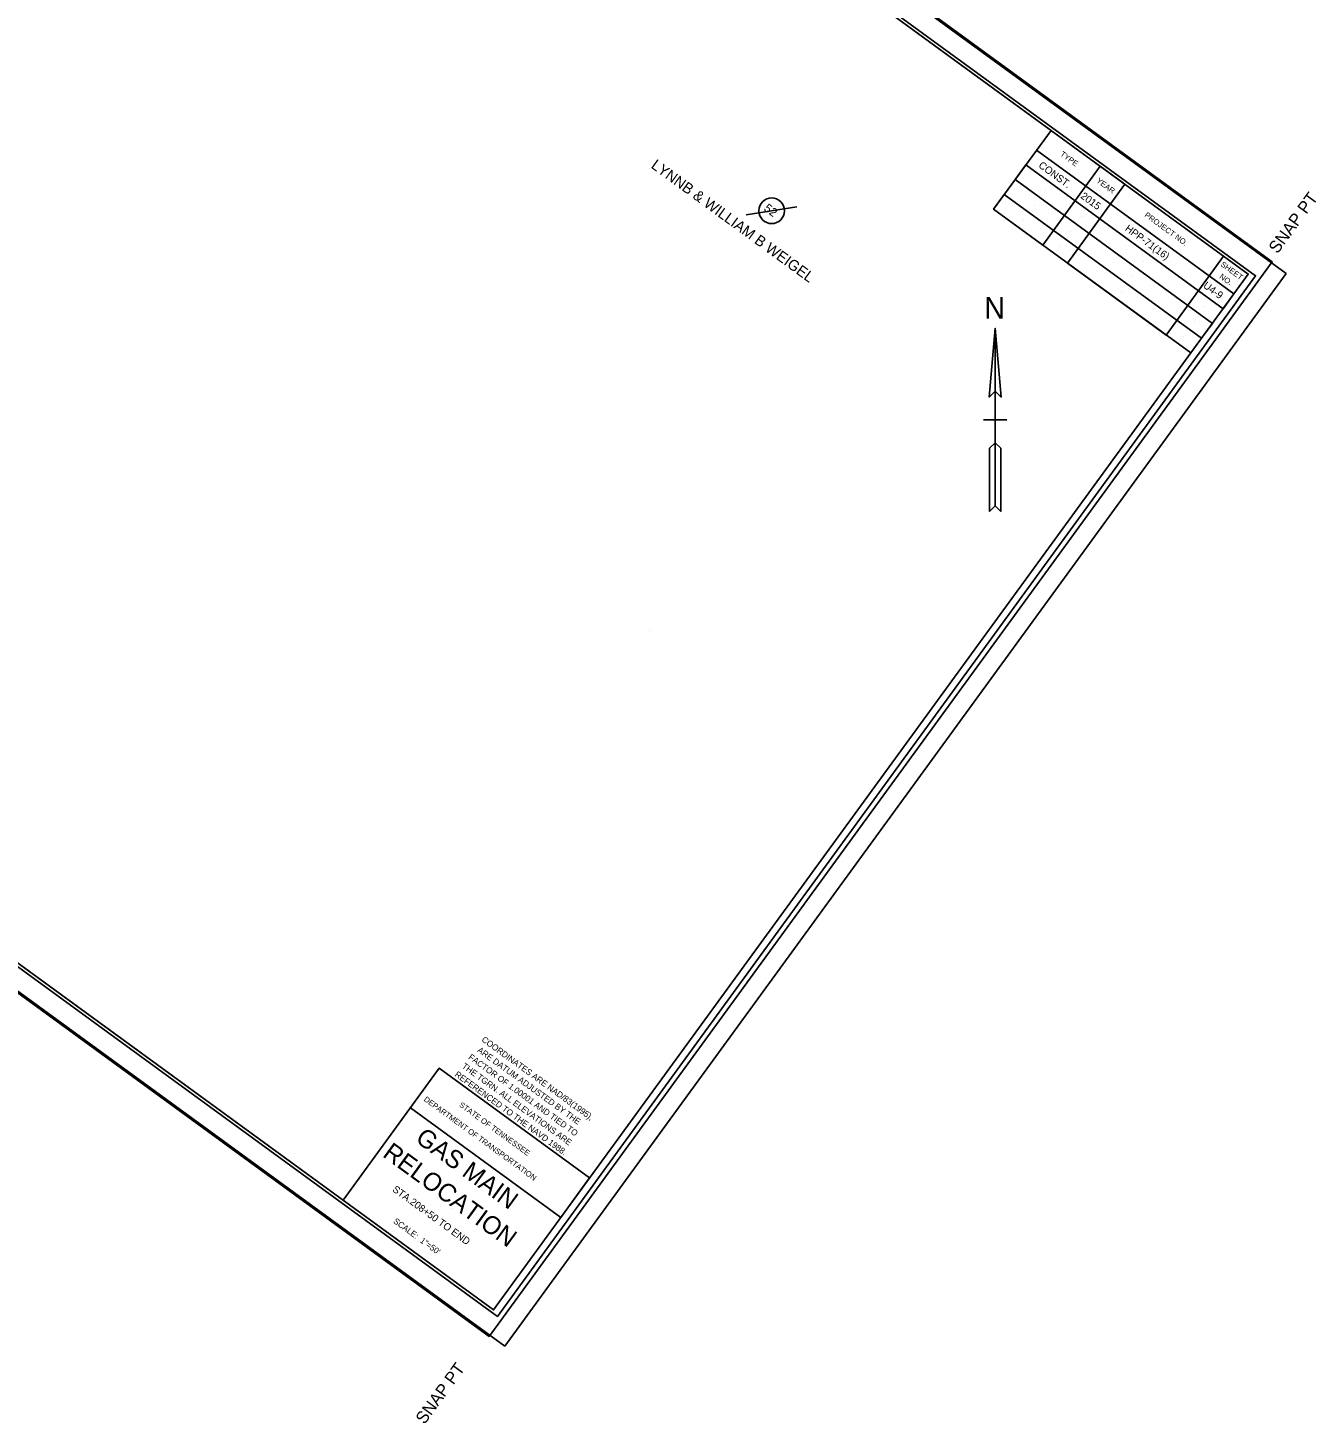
# Model space of a CAD drawing. Extents: x 2632015 to 2634135, y 566161 to 568172.
# Drawn here: x 2633079 to 2634135, y 566161 to 567305 of the extents above; entities that cross this region are included whole.
import ezdxf

# ---------------------------------------------------------------- set-up
doc = ezdxf.new("R2010")
doc.units = 0
for name, color, linetype in [('DESIGN - CENTERLINE - Proposed Text', 7, 'Continuous'), ('DESIGN - SCRATCH - User 1', 7, 'Continuous'), ('DESIGN - SHEET - Corner Text', 7, 'Continuous'), ('DESIGN - SHEET - Light Grid', 7, 'Continuous'), ('DESIGN - SHEET - Linework', 7, 'Continuous'), ('DESIGN - SHEET - Plot Shape', 7, 'Continuous'), ('SURVEY - PROPERTY - Owners', 7, 'Continuous'), ('SURVEY - PROPERTY - Tract Numbers', 7, 'Continuous')]:
    doc.layers.add(name, color=color, linetype=linetype)

msp = doc.modelspace()

# ---------------------------------------------------------------- linework, layer by layer
at = {"layer": 'DESIGN - CENTERLINE - Proposed Text'}
for p, q in [((2633871.9, 566983.6), (2633862.4, 566983.6)), ((2633881.3, 566983.6), (2633871.9, 566983.6))]:
    msp.add_line(p, q, dxfattribs=at)
msp.add_lwpolyline([(2633871.9, 567058.6), (2633867, 567002.3), (2633871.9, 567007.2), (2633876.8, 567002.3), (2633871.9, 567058.6), (2633871.9, 566913.1), (2633876.4, 566908.6), (2633876.4, 566960.3), (2633871.9, 566964.9), (2633867.3, 566960.3), (2633867.3, 566908.6), (2633871.9, 566913.1)], dxfattribs=at)
for points in [[(2633871.9, 567007.2), (2633876.8, 567002.3), (2633871.9, 567058.6)], [(2633867.3, 566908.6), (2633871.9, 566913.1), (2633871.9, 566964.9), (2633867.3, 566960.3)]]:
    msp.add_lwpolyline(points, close=True, dxfattribs=at)
at = {"layer": 'DESIGN - SCRATCH - User 1'}
for p, q in [((2633921.6, 567183.9), (2633921.6, 567183.9)), ((2633912.8, 567171.7), (2633912.8, 567171.7)), ((2633903.9, 567159.6), (2633903.9, 567159.6)), ((2633951.5, 567162.1), (2633951.5, 567162.1)), ((2633942.7, 567149.9), (2633942.7, 567149.9)), ((2633895.1, 567147.5), (2633895.1, 567147.5)), ((2633933.8, 567137.8), (2633933.8, 567137.8)), ((2633925, 567125.7), (2633925, 567125.7)), ((2634002, 567125.3), (2634002, 567125.3)), ((2633993.2, 567113.1), (2633993.2, 567113.1)), ((2633984.3, 567101), (2633984.3, 567101)), ((2633975.5, 567088.9), (2633975.5, 567088.9)), ((2634052.5, 567088.5), (2634052.5, 567088.5)), ((2634043.7, 567076.3), (2634043.7, 567076.3)), ((2634034.8, 567064.2), (2634034.8, 567064.2)), ((2634026, 567052.1), (2634026, 567052.1)), ((2633588.8, 566810.8), (2633588.8, 566810.8)), ((2633426.8, 566337.2), (2633426.8, 566337.2))]:
    msp.add_line(p, q, dxfattribs=at)
at = {"layer": 'DESIGN - SHEET - Light Grid'}
msp.add_lwpolyline([(2632118.4, 567229.6), (2633464, 566249), (2634085.3, 567101.7), (2632739.7, 568082.2)], close=True, dxfattribs=at)
at = {"layer": 'DESIGN - SHEET - Linework'}
for p, q in [((2632655.7, 568163.5), (2634110.4, 567103.4)), ((2632015.3, 567284.7), (2633470, 566224.6)), ((2634110.4, 567103.4), (2633470, 566224.6))]:
    msp.add_line(p, q, dxfattribs=at)
for points in [[(2632807, 568030.1), (2632188.6, 567181.6), (2633460.8, 566254.4), (2634079.2, 567103), (2632807, 568030.1)], [(2633917.6, 567220.8), (2633870.5, 567156.2), (2634032.1, 567038.4), (2634079.2, 567103), (2634059, 567117.7), (2634011.9, 567053.1), (2633931.1, 567112), (2633978.2, 567176.6), (2633958, 567191.4), (2633910.9, 567126.7), (2633870.5, 567156.2), (2633879.3, 567168.3), (2634040.9, 567050.5), (2634049.8, 567062.6), (2633888.1, 567180.4), (2633897, 567192.5), (2634058.6, 567074.7), (2634067.4, 567086.9), (2633905.8, 567204.6)], [(2633337.6, 566344.3), (2633416.3, 566452.3), (2633539.5, 566362.5), (2633516, 566330.1), (2633392.7, 566419.9)]]:
    msp.add_lwpolyline(points, dxfattribs=at)
at = {"layer": 'DESIGN - SHEET - Plot Shape'}
for points in [[(2632724.9, 568114.3), (2634098.8, 567113.1), (2633457.2, 566232.7), (2632083.3, 567233.9)], [(2632738.3, 568080.2), (2634079.2, 567103), (2633460.8, 566254.4), (2632119.9, 567231.6)]]:
    msp.add_lwpolyline(points, close=True, dxfattribs=at)
at = {"layer": 'SURVEY - PROPERTY - Tract Numbers'}
msp.add_line((2633667.9, 567151.6), (2633709.4, 567158.1), dxfattribs=at)
msp.add_circle((2633688.7, 567154.9), 10.5, dxfattribs=at)

# ---------------------------------------------------------------- texts
at = {"layer": 'DESIGN - CENTERLINE - Proposed Text'}
msp.add_text('N', height=17.7, dxfattribs=at).set_placement((2633862.8, 567066.6))
at = {"layer": 'DESIGN - SHEET - Corner Text'}
for s, height, rotation, p in [('CONST.', 6, 323.918, (2633906.8, 567191)), ('TYPE', 4.5, 323.918, (2633924.7, 567200.5)), ('YEAR', 4.5, 323.918, (2633954.3, 567178.7)), ('  SNAP PT', 10, 53.918, (2634098.8, 567113.1)), ('2015', 6, 323.918, (2633941.3, 567165.8)), ('PROJECT NO.', 4.5, 323.918, (2633993.8, 567150.5)), ('HPP-71(16)', 6, 323.918, (2633977.7, 567139.2)), ('NO.', 4.5, 323.918, (2634055.2, 567100.1)), ('SHEET', 4.5, 323.918, (2634056.1, 567110.1)), ('U4-9', 6, 323.918, (2634041.8, 567092.5)), ('COORDINATES ARE NAD/83(1995),', 5, 323.918, (2633450.5, 566474.8)), ('FACTOR OF 1.00001 AND TIED TO', 5, 323.918, (2633439.7, 566460.4)), ('ARE DATUM ADJUSTED BY THE', 5, 323.918, (2633447, 566466.2)), ('THE TGRN. ALL ELEVATIONS ARE', 5, 323.918, (2633434.4, 566453.1)), ('REFERENCED TO THE NAVD 1988.', 5, 323.918, (2633428.5, 566446.3)), ('DEPARTMENT OF TRANSPORTATION', 4.5, 323.918, (2633403.2, 566426)), ('STATE OF TENNESSEE', 4.5, 323.918, (2633432.2, 566421.4)), ('GAS MAIN ', 14.76, 323.918, (2633395.9, 566392.8)), ('RELOCATION', 14.76, 323.918, (2633369.1, 566380.5)), ('STA.208+50 TO END', 5.905, 323.918, (2633377.4, 566352)), ('SCALE:  1"=50\'', 4.921, 323.918, (2633378.2, 566326.1)), ('SNAP PT  ', 10, 53.918, (2633404.2, 566160))]:
    msp.add_text(s, height=height, rotation=rotation, dxfattribs=at).set_placement(p)
at = {"layer": 'SURVEY - PROPERTY - Owners'}
msp.add_text('LYNNB & WILLIAM B WEIGEL', height=8.75, rotation=323.918, dxfattribs=at).set_placement((2633589.2, 567190.6))
at = {"layer": 'SURVEY - PROPERTY - Tract Numbers'}
msp.add_text('52', height=7, rotation=323.918, dxfattribs=at).set_placement((2633681.7, 567155.6))

doc.saveas('drawing.dxf')
